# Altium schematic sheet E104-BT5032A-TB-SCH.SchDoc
size A4
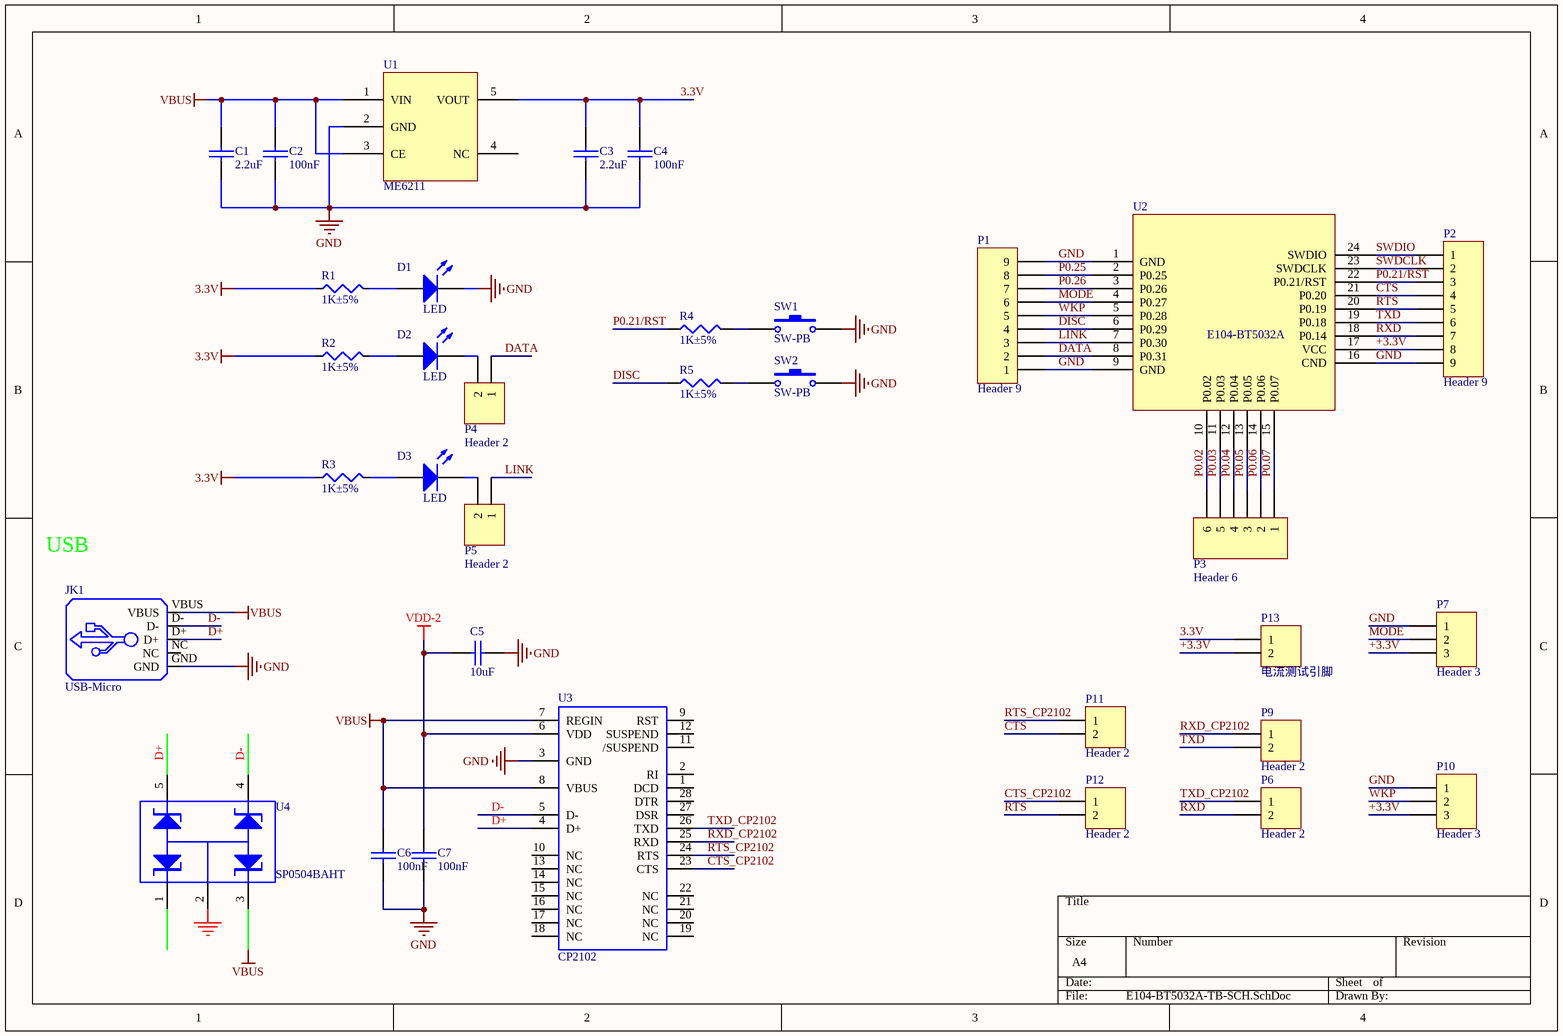
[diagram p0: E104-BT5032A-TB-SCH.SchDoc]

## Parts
C1  2.2uF  [E-CAP-0603]
C2  100nF  [0402A-C]
C3  2.2uF  [e-cap-0603]
C4  100nF  [0402A-C]
C5  10uF  [E-CAP-0603]
C6  100nF  [0402A-C]
C7  100nF  [0402A-C]
D1  LED  [E-LED-0805]
D2  LED  [E-LED-0805]
D3  LED  [E-LED-0805]
JK1  USB-Micro  [Micro USB-5SB]
P1  Header 9  [D-2.54-9P-G]
P2  Header 9  [D-2.54-9P-G]
P3  Header 6  [HDR1X6]
P4  Header 2  [HDR1X2]
P5  Header 2  [HDR1X2]
P6  Header 2  [HDR1X2]
P7  Header 3  [HDR1X3]
P9  Header 2  [HDR1X2]
P10  Header 3  [HDR1X3]
P11  Header 2  [HDR1X2]
P12  Header 2  [HDR1X2]
P13  电流测试引脚  [HDR1X2]
R1  1K±5%  [E-RES-0402]
R2  1K±5%  [E-RES-0402]
R3  1K±5%  [E-RES-0402]
R4  1K±5%  [E-RES-0402]
R5  1K±5%  [E-RES-0402]
SW1  SW-PB  [swich]
SW2  SW-PB  [swich]
U1  ME6211  [E-SOT23-5]
U2  E104-BT5032A  [E104-BT5032A]
U3  CP2102  [QFN28]
U4  SP0504BAHT  [SP0504]

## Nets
3.3V: C3.1 C4.1 P13.1 R1.1 R2.1 R3.1 U1.5(VOUT)
GND: C1.2 C2.2 C3.2 C4.2 C5.2 C6.2 C7.2 D1.K JK1.GND P1.1 P1.9 P2.9 P7.1 P10.1 SW1.2 SW2.2 U1.2(GND) U2.1(GND) U2.9(GND) U2.16(CND) U3.3(GND) U4.2
VBUS: C1.1 C2.1 C6.1 JK1.VBUS U1.1(VIN) U1.3(CE) U3.7(REGIN) U3.8(VBUS) U4.3
VDD-2: C5.1 C7.1 U3.6(VDD)
+3.3V: P2.8 P7.3 P10.3 P13.2 U2.17(VCC)
CTS: P2.4 P11.2 U2.21(P0.20)
CTS_CP2102: P12.1 U3.23(CTS)
D+: JK1.D+ U3.4(D+) U4.5
D-: JK1.D- U3.5(D-) U4.4
DATA: P1.2 P4.1 U2.8(P0.31)
DISC: P1.4 R5.1 U2.6(P0.29)
LINK: P1.3 P5.1 U2.7(P0.30)
MODE: P1.6 P7.2 U2.4(P0.27)
P0.02: P3.6 U2.10(P0.02)
P0.03: P3.5 U2.11(P0.03)
P0.04: P3.4 U2.12(P0.04)
P0.05: P3.3 U2.13(P0.05)
P0.06: P3.2 U2.14(P0.06)
P0.07: P3.1 U2.15(P0.07)
P0.21/RST: P2.3 R4.1 U2.22(P0.21/RST)
P0.25: P1.8 U2.2(P0.25)
P0.26: P1.7 U2.3(P0.26)
RTS: P2.5 P12.2 U2.20(P0.19)
RTS_CP2102: P11.1 U3.24(RTS)
RXD: P2.7 P6.2 U2.18(P0.14)
RXD_CP2102: P9.1 U3.25(RXD)
SWDCLK: P2.2 U2.23(SWDCLK)
SWDIO: P2.1 U2.24(SWDIO)
TXD: P2.6 P9.2 U2.19(P0.18)
TXD_CP2102: P6.1 U3.26(TXD)
WKP: P1.5 P10.2 U2.5(P0.28)
NetD1_A: D1.A R1.2
NetD2_A: D2.A R2.2
NetD2_K: D2.K P4.2
NetD3_A: D3.A R3.2
NetD3_K: D3.K P5.2
NetR4_2: R4.2 SW1.1
NetR5_2: R5.2 SW2.1

Not connected (* = marked no-connect by the designer): JK1 NC; U1 4(NC); U3 1(DCD) 2(RI) 9(RST) 10(NC) 11(/SUSPEND) 12(SUSPEND) 13(NC) 14(NC) 15(NC) 16(NC) 17(NC) 18(NC) 19(NC) 20(NC) 21(NC) 22(NC) 27(DSR) 28(DTR); U4 1

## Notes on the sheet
- USB

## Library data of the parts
C1-C7 = cap0603: Capacitor
D1-D3 = LED1: Typical RED GaAs LED
JK1 = USB-MINI
P1 P2 = Header 9: Header, 9-Pin
P3 = Header 6: Header, 6-Pin
P4-P6 P9 P11-P13 = Header 2: Header, 2-Pin
P7 P10 = Header 3: Header, 3-Pin
R1-R3 = res0603
R4 R5 = res0402
SW1 SW2 = SW-PB: Switch
U1 = HT7233
U4 = SP0504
